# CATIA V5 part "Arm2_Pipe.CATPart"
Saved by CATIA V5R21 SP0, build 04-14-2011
Part number: Arm2_Pipe
Bounding box of the stored display mesh (mm): x 0 to 135, y -12.5 to 12.5, z -12.409 to 12.409
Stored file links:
  K:\Arm_Detailed_Design_Assembly_Manu\Arm2_Pipe.CATPart
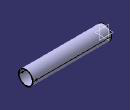
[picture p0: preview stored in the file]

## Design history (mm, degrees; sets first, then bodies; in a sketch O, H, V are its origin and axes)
Body1 (main body)
  Sketch1 on yz-plane, origin (0, 0, 0), H (0, 1, 0), V (0, 0, 1)
    circle A1 centre (0, 0) radius 11.5
    circle A2 centre (0, 0) radius 12.5
    radius A1 = 11.5
    radius A2 = 12.5
  Pad1: profile Sketch1, direction (1, 0, 0), length 135
  Sketch2 on zx-plane, origin (0, 0, 0), H (-1, 0, 0), V (0, 0, 1)
    circle A1 centre (-6, 0) radius 1.5
    point P1 (-6, 0)
    circle A2 centre (-129, 0) radius 1.5
    point P2 (-129, 0)
    reference projected line E1 (-135, -12.5) -> (-135, 12.5) from edge [face of Pad1 from Sketch1.A2 | end face of Pad1]
    radius A1 = 1.5
    distance V P1 = 6
    radius A2 = 1.5
    distance E1 P2 = 6
    coincidence: P1 H, P2 H
  Pocket1: profile Sketch2, direction (0, -1, 0), length 50, mirrored extent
